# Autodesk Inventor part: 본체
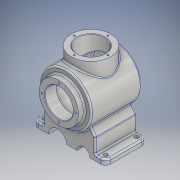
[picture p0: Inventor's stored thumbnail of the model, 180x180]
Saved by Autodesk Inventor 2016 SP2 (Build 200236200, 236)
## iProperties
Created: 2018-08
Part Number: 본체
Material: 알루미늄 6061
Document SubType Name: Modeling
Designer: Administrator
Density: 2.7 g/cm^3
Appearance: 알루미늄 - 평지
Mass: 1879.09 g
Surface Area: 1087.45 cm^2
Volume: 695.959 cm^3
Author: Administrator
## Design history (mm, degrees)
sketch "스케치1"
  geometry: L1 (12, 132)-(108.671, 132); L2 (120, 82)-(0, 82); L3 (0, 82)-(0, 120); L4 (12, 132)-(12, 120); L5 (12, 120)-(0, 120); L6 (102.163, 122)-(22, 122); L7 (22, 122)-(22, 109); L8 (0, 109)-(22, 109); L9 (0, 82)-(0, 109); A1 r 116 centre (4, 82) between (120, 82) and (108.671, 132); A2 r 106 centre (4, 82) between (110, 82) and (102.163, 122); 1 further point
  constraints: 18 end point, 4 point on circle, 4 point on line, 3 vertical, 2 centre point, 2 horizontal, 1 parallel
  dimensions: "d0" = 82 distance from line of point (0, 0) L2; "d2" = 12 distance of L4.end L3.end; "d4" = 76 diameter of L5 L2; "d5" = 100 diameter of L1 L2; "d6" = 116 radius of A1; "d7" = 120 distance from line of L3 L2.start; "d8" = 10 radial gap between concentric circles of A1 A2; "d9" = 22 distance of L8.start L7.end; "d10" = 54 diameter of L8 L2; "d11" = 10 distance between parallel lines of L1 L6; "d131" = 108 distance from line of L2.start L4 (derived)
revolve "회전1" stored, may be unused: angle "d12" = 90 deg
sketch "스케치2"
  geometry: L1 (0, 0)-(32, 0); L2 (0, -70)-(0, 0); L3 (10, -70)-(10, -50); L4 (10, -50)-(38.563, -50); L5 (10, -70)-(0, -70); L6 (38.563, -50)-(52.41, -40.304); L7 (0, 70)-(0, 0); L8 (10, 70)-(10, 50); L9 (10, 50)-(38.563, 50); L10 (10, 70)-(0, 70); L11 (38.563, 50)-(52.41, 40.304); A1 r 50 centre (82, 0) between (32, 0) and (52.41, -40.304) reference
  constraints: 22 end point, 5 symmetric about line, 2 horizontal, 2 point on circle, 1 perpendicular, 1 vertical
  dimensions: "d13" = 82 distance from line of L2 A1.centre; "d14" = 70 distance of L2.start L1.start; "d15" = 10 distance of L3.start L2.start; "d16" = 20 distance of L3.start L3.end; "d19" = 35 deg angle of L5 L6
node "작업 평면1"
sketch "스케치3"
  geometry: L1 (0, -82)-(-70, -82); L2 (-70, -82)-(-70, -72); L3 (-70, -72)-(-50, -72); L4 (-50, -72)-(-50, -43.437); L5 (0, -82)-(0, -50); L6 (-70, -72)-(-40.304, -29.59); L7 (0, -82)-(70, -82); L8 (70, -82)-(70, -72); L9 (70, -72)-(50, -72); L10 (50, -72)-(50, -43.437); L11 (70, -72)-(40.304, -29.59); A1 r 50 centre (0, 0) between (0, -50) and (-40.304, -29.59) reference
  constraints: 22 end point, 5 symmetric about line, 3 perpendicular, 2 point on circle, 2 point on line, 1 horizontal, 1 vertical
  dimensions: "d21" = 70 distance of L1.start L1.end; "d22" = 10 distance of L1.end L2.end; "d23" = 35 deg angle of L2 L6; "d24" = 20 distance of L2.end L3.end
extrude "돌출1" join sketch "스케치3" stored distance "d25" = 80; taper "d26" = 0 deg
revolve "회전2" stored, may be unused: angle "d27" = 90 deg
sketch "스케치4"
  geometry: L1 (-70, -82)-(70, -82) reference; C1 r 17.5 at (-22.5, -82); C2 r 12.5 at (27.5, -82); 1 further point
  constraints: 2 centre point, 2 point on line
  dimensions: "d28" = 35 diameter of C1; "d29" = 22.5 distance of point (0, -82) C1.centre; "d30" = 25 diameter of C2; "d31" = 27.5 distance of point (0, -82) C2.centre
extrude "돌출2" cut sketch "스케치4" distance "d32" = 140; taper "d33" = 0 deg
node "작업 평면2"
sketch "스케치6"
  geometry: L1 (-22, 5)-(112.534, 5); L2 (-22, -33)-(-22, 43) reference; C1 r 38 at (40, 5)
  constraints: 2 end point, 1 centre point, 1 horizontal, 1 point on line
  dimensions: "d35" = 76 diameter of C1; "d36" = 62 distance from line of L2 C1.centre
extrude "돌출3" join sketch "스케치6" stored distance "d37" = 140; taper "d38" = 0 deg; dims "d130" = -2
hole "구멍1" diameter "d41" = 54; stored, may be unused: countersink angle "d45" = 90 deg, drill point angle "d47" = 118 deg; dims "d39" = 10, "d40" = 10, "d42" = 6, "d43" = 4, "d44" = 2, "d46" = 8
sketch "스케치7" dims "d48" = 65
  geometry: L1 (0, 0)-(0, 32.5); C1 r 38 at (0, 0) reference; C2 r 3.693 at (0, 32.5); C3 r 3.693 at (-32.5, 0); C4 r 3.693 at (0, -32.5); C5 r 3.693 at (32.5, 0); 1 further point
  constraints: 4 centre point, 2 coincident, 2 end point, 1 vertical, 1 vertical alignment, 11 other
  dimensions: "d51" = 360 deg dimension on C1.centre C2.centre (derived)
sketch "스케치8" dims "d53" = 65
  geometry: L1 (0, 0)-(0, 32.5); C1 r 38 at (0, 0) reference; C2 r 4.049 at (0, 32.5); C3 r 4.049 at (-32.5, 0); C4 r 4.049 at (0, -32.5); C5 r 4.049 at (32.5, 0); 1 further point
  constraints: 4 centre point, 2 coincident, 2 end point, 1 vertical, 1 vertical alignment, 11 other
  dimensions: "d56" = 360 deg dimension on C1.centre C2.centre (derived)
hole "구멍2" sketch "스케치8" at (-32.5, 0), (0, 32.5), (32.5, 0), (0, -32.5) diameter "d58" = 3.242; stored, may be unused: countersink angle "d62" = 90 deg, drill point angle "d64" = 118 deg; dims "d59" = 8, "d60" = 4, "d61" = 2, "d63" = 10
hole "구멍3" sketch "스케치7" diameter "d65" = 3.242; stored, may be unused: countersink angle "d69" = 90 deg, drill point angle "d71" = 118 deg; dims "d66" = 8, "d67" = 4, "d68" = 2, "d70" = 10
fillet "모깎기1" dims "d72" = 3
fillet "모깎기2" dims "d73" = 3
fillet "모깎기3" dims "d74" = 10
hole "구멍4" diameter "d77" = 8; stored, may be unused: countersink angle "d81" = 90 deg, drill point angle "d83" = 0 deg; dims "d75" = 10, "d76" = 10, "d78" = 8, "d79" = 4, "d80" = 2, "d82" = 10
hole "구멍5" diameter "d86" = 8; stored, may be unused: countersink angle "d90" = 90 deg, drill point angle "d92" = 0 deg; dims "d84" = 10, "d85" = 10, "d87" = 8, "d88" = 4, "d89" = 2, "d91" = 10
hole "구멍6" diameter "d95" = 8; stored, may be unused: countersink angle "d99" = 90 deg, drill point angle "d101" = 0 deg; dims "d93" = 10, "d94" = 10, "d96" = 8, "d97" = 4, "d98" = 2, "d100" = 10
hole "구멍7" diameter "d104" = 8; stored, may be unused: countersink angle "d108" = 90 deg, drill point angle "d110" = 0 deg; dims "d102" = 10, "d103" = 10, "d105" = 8, "d106" = 4, "d107" = 2, "d109" = 10
fillet "모깎기4" dims "d111" = 3
fillet "모깎기5" dims "d112" = 3
fillet "모깎기6" dims "d113" = 3
fillet "모깎기7" dims "d114" = 3
fillet "모깎기8" dims "d115" = 3
chamfer "모따기1" distance "d116" = 1; stored, may be unused: second distance "d117" = 2, angle "d118" = 45 deg
chamfer "모따기2" distance "d119" = 1; stored, may be unused: second distance "d120" = 2, angle "d121" = 45 deg
node "작업 평면3"
sketch "스케치9"
  geometry: L1 (0, 0)-(0, -66.979); L2 (0, 0)-(0, 47.875); L3 (0, 0)-(32.5, 0); C1 r 50 at (0, 0) reference; A1 r 32.5 centre (0, 0) between (0, -32.5) and (32.5, 0); 1 further point
  constraints: 6 end point, 2 point on circle, 2 vertical, 1 centre point, 1 coincident, 1 point on line, 1 other
  dimensions: "d122" = 65 diameter of A1
feature "엠보싱1" sketch "스케치9" dims "d13" = 82, "d14" = 70, "d15" = 10, "d16" = 20, "d19" = 35 deg, "d123" = 0.5, "d124" = 0
node "직접 편집1"
node "직접 편집2"
node "직접 편집3"
node "솔리드1"
mirror "대칭1"
node "투영된 루프1"
feature "이동1" dims "d127" = 2
feature "이동2" dims "d130" = -2
feature "이동3" dims "d132" = -2
feature "이동4" dims "d135" = -2
feature "이동5" dims "d138" = -2
other parameters: "d20" = -62, "d34" = -147, "d125" = 0, "d126" = 0, "d128" = 0, "d129" = 0, "d133" = 0, "d134" = 0, "d136" = 0, "d137" = 0, "d139" = 0, "d140" = 0
